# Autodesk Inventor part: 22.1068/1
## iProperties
Created: 2007-01
Part Number: 22.1068/1
Document SubType Name: Modeling
Designer: Andy Moles
Material: ABS Plastic
Density: 1.06 g/cm^3
Mass: 14.0467 g
Surface Area: 102.239 cm^2
Volume: 13.2516 cm^3
Vendor: S
Description: END CAP 45X90 GRAY
Author: Andy Moles
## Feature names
1. Extrusion1
2. Fillet1
3. Fillet2
4. Extrusion2
5. Fillet3
6. Mirror1
7. Mirror2
